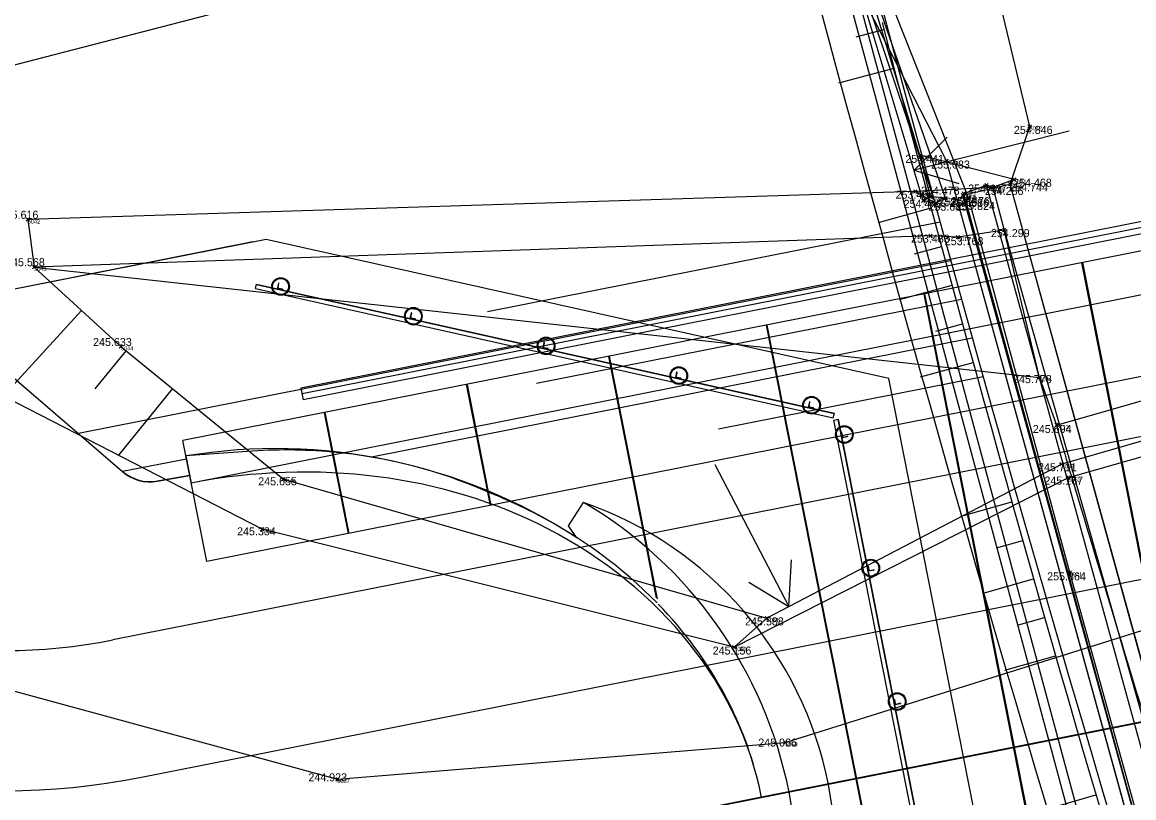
# Model space of a CAD drawing. Extents: x -809973 to -809318, y -1011363 to -1010505.
# Drawn here: x -809855.63 to -809841.74, y -1010988.6 to -1010978.91 of the extents above; entities that cross this region are included whole.
import ezdxf

# ---------------------------------------------------------------- set-up
doc = ezdxf.new("R2010")
doc.units = 0
for name, color, linetype in [('18b - zaměření - čísla bodů', 7, 'Continuous'), ('18c - zaměření - výšky', 7, 'Continuous'), ('21 - sítě', 7, 'Continuous'), ('21a - sítě - DKK - ČD Telematika a.s.', 7, 'Continuous'), ('21b - sítě - SŽDC - SSZT', 7, 'Continuous'), ('SO04 - Železniční spodek', 7, 'Continuous'), ('SO05 - Úprava kabelů', 7, 'Continuous'), ('SO_01', 7, 'Continuous'), ('stav_stav', 7, 'Continuous')]:
    doc.layers.add(name, color=color, linetype=linetype)

# ---------------------------------------------------------------- blocks, each defined once
blk = doc.blocks.new('POINT_DISPLAY')
for p, q in [((-0.021, -0.021), (0.021, 0.021)), ((-0.021, 0.021), (0.021, -0.021))]:
    blk.add_line(p, q)

msp = doc.modelspace()

# ---------------------------------------------------------------- linework, layer by layer
at = {"layer": '21 - sítě'}
msp.add_lwpolyline([(-809832.875, -1011017.263), (-809833.494, -1011015.746), (-809838.391, -1011005.426), (-809840.703, -1011001.729), (-809840.806, -1011000.123), (-809839.446, -1010997.434), (-809844.081, -1010980.644), (-809845.074, -1010978.711), (-809846.471, -1010977.412)], dxfattribs=at)
at = {"layer": '21a - sítě - DKK - ČD Telematika a.s.'}
msp.add_lwpolyline([(-809840.802, -1011000.183), (-809839.446, -1010997.434), (-809844.081, -1010980.644), (-809845.074, -1010978.711), (-809846.471, -1010977.412)], dxfattribs=at)
at = {"layer": '21b - sítě - SŽDC - SSZT'}
msp.add_lwpolyline([(-809840.802, -1011000.183), (-809839.446, -1010997.434), (-809844.081, -1010980.644), (-809845.074, -1010978.711), (-809846.471, -1010977.412)], dxfattribs=at)
at = {"layer": 'SO04 - Železniční spodek'}
for points in [[(-809845.21, -1010979.093), (-809844.863, -1010979.002)], [(-809845.426, -1010979.667), (-809844.736, -1010979.486)], [(-809844.932, -1010981.411), (-809844.272, -1010981.231)], [(-809844.479, -1010981.806), (-809844.142, -1010981.714)], [(-809844.669, -1010982.376), (-809844.011, -1010982.197)], [(-809844.214, -1010982.77), (-809843.88, -1010982.679)], [(-809844.407, -1010983.341), (-809843.747, -1010983.161)], [(-809843.896, -1010985.081), (-809843.263, -1010984.902)], [(-809843.455, -1010985.475), (-809843.128, -1010985.383)], [(-809843.624, -1010986.043), (-809842.992, -1010985.864)], [(-809843.179, -1010986.437), (-809842.854, -1010986.345)], [(-809843.352, -1010987.005), (-809842.717, -1010986.826)], [(-809842.826, -1010988.74), (-809842.213, -1010988.561)]]:
    msp.add_lwpolyline(points, dxfattribs=at)
for centre, radius, start, end in [((-809453.305, -1010872.818), 406.4, 193.63597, 201.43276), ((-809524.411, -1010895.31), 331.2, 194.62152, 202.36706)]:
    msp.add_arc(centre, radius, start, end, dxfattribs=at)
at = {"layer": 'SO05 - Úprava kabelů'}
for points in [[(-809832.452, -1011018.3), (-809834.599, -1011012.541), (-809836.558, -1011007.657), (-809839.63, -1011000.177), (-809840.754, -1010995.474), (-809845.885, -1010976.431), (-809847.466, -1010970.457), (-809849.998, -1010958.97), (-809853.746, -1010939.574), (-809862.448, -1010886.367), (-809861.681, -1010881.903), (-809870.184, -1010824.906)], [(-809832.343, -1011018.259), (-809834.49, -1011012.499), (-809836.45, -1011007.613), (-809839.519, -1011000.141), (-809840.641, -1010995.445), (-809845.773, -1010976.401), (-809847.353, -1010970.429), (-809849.884, -1010958.947), (-809853.631, -1010939.554), (-809862.33, -1010886.367), (-809861.563, -1010881.905), (-809870.069, -1010824.889)]]:
    msp.add_lwpolyline(points, dxfattribs=at)
at = {"layer": 'SO_01'}
for p, q in [((-809845.406, -1010976.768), (-809858.889, -1010980.268)), ((-809827.206, -1010978.912), (-809853.624, -1010984.137)), ((-809829.834, -1010979.065), (-809852.149, -1010983.48)), ((-809829.819, -1010979.139), (-809852.135, -1010983.553)), ((-809829.804, -1010979.213), (-809852.12, -1010983.627)), ((-809827.101, -1010979.442), (-809853.52, -1010984.667)), ((-809826.907, -1010980.423), (-809853.326, -1010985.648)), ((-809844.161, -1010981.408), (-809849.817, -1010982.527)), ((-809852.751, -1010981.656), (-809856.789, -1010982.455)), ((-809844.027, -1010981.891), (-809854.93, -1010984.048)), ((-809842.392, -1010981.916), (-809840.149, -1010993.254)), ((-809842.382, -1010981.914), (-809840.14, -1010993.252)), ((-809831.291, -1010982.037), (-809848.657, -1010985.472)), ((-809852.717, -1010982.239), (-809852.704, -1010982.181)), ((-809852.705, -1010982.186), (-809845.483, -1010983.8)), ((-809852.704, -1010982.181), (-809845.482, -1010983.795)), ((-809852.717, -1010982.239), (-809845.495, -1010983.853)), ((-809844.364, -1010982.306), (-809842.121, -1010993.644)), ((-809844.354, -1010982.304), (-809842.111, -1010993.642)), ((-809843.893, -1010982.374), (-809849.204, -1010983.425)), ((-809856.677, -1010982.547), (-809854.379, -1010984.522)), ((-809846.336, -1010982.696), (-809844.093, -1010994.034)), ((-809846.326, -1010982.694), (-809844.083, -1010994.032)), ((-809843.759, -1010982.857), (-809851.267, -1010984.342)), ((-809848.307, -1010983.086), (-809847.711, -1010986.1)), ((-809848.298, -1010983.084), (-809847.698, -1010986.114)), ((-809850.083, -1010983.437), (-809849.784, -1010984.948)), ((-809850.073, -1010983.435), (-809849.774, -1010984.946)), ((-809843.623, -1010983.34), (-809846.931, -1010983.995)), ((-809852.149, -1010983.48), (-809852.12, -1010983.627)), ((-809851.859, -1010983.788), (-809851.56, -1010985.299)), ((-809851.849, -1010983.786), (-809851.55, -1010985.297)), ((-809845.495, -1010983.853), (-809845.482, -1010983.795)), ((-809845.489, -1010983.883), (-809845.43, -1010983.871)), ((-809843.762, -1010992.614), (-809845.489, -1010983.883)), ((-809843.708, -1010992.603), (-809845.435, -1010983.872)), ((-809843.703, -1010992.602), (-809845.43, -1010983.871)), ((-809853.326, -1010985.648), (-809853.624, -1010984.137)), ((-809852.82, -1010984.272), (-809853.587, -1010984.329)), ((-809851.762, -1010984.279), (-809851.71, -1010984.541)), ((-809851.751, -1010984.28), (-809851.699, -1010984.541)), ((-809853.579, -1010984.369), (-809854.379, -1010984.522)), ((-809853.587, -1010984.329), (-809853.52, -1010984.667)), ((-809853.539, -1010984.571), (-809853.967, -1010984.646)), ((-809849.818, -1010984.777), (-809849.789, -1010984.922)), ((-809849.807, -1010984.782), (-809849.778, -1010984.926)), ((-809848.657, -1010985.472), (-809854.501, -1010986.627)), ((-809830.791, -1010985.512), (-809846.92, -1010988.702)), ((-809832.198, -1010985.784), (-809846.393, -1010988.591)), ((-809846.393, -1010988.591), (-809853.822, -1010990.061))]:
    msp.add_line(p, q, dxfattribs=at)
for points in [[(-809847.89, -1010966.747), (-809847.781, -1010967.211), (-809847.549, -1010968.191), (-809847.314, -1010969.171), (-809847.077, -1010970.15), (-809846.837, -1010971.129), (-809846.595, -1010972.108), (-809846.351, -1010973.086), (-809846.104, -1010974.063), (-809845.854, -1010975.04), (-809845.602, -1010976.016), (-809845.348, -1010976.992), (-809845.091, -1010977.967), (-809844.832, -1010978.937)], [(-809844.802, -1010983.363), (-809852.585, -1010981.623), (-809856.789, -1010982.455), (-809854.379, -1010984.522)], [(-809852.427, -1010982.171), (-809852.43, -1010982.17), (-809852.445, -1010982.239)], [(-809852.435, -1010982.225), (-809852.424, -1010982.176)], [(-809852.445, -1010982.239), (-809852.377, -1010982.254), (-809852.376, -1010982.252)], [(-809852.38, -1010982.246), (-809852.428, -1010982.235)], [(-809850.768, -1010982.542), (-809850.771, -1010982.541), (-809850.786, -1010982.609)], [(-809850.786, -1010982.609), (-809850.718, -1010982.625), (-809850.717, -1010982.622)], [(-809850.776, -1010982.595), (-809850.765, -1010982.547)], [(-809850.721, -1010982.617), (-809850.769, -1010982.606)], [(-809849.109, -1010982.912), (-809849.112, -1010982.912), (-809849.127, -1010982.98)], [(-809849.117, -1010982.966), (-809849.106, -1010982.918)], [(-809849.127, -1010982.98), (-809849.059, -1010982.996), (-809849.058, -1010982.993)], [(-809849.062, -1010982.988), (-809849.11, -1010982.977)], [(-809847.45, -1010983.283), (-809847.453, -1010983.283), (-809847.468, -1010983.351)], [(-809847.458, -1010983.337), (-809847.447, -1010983.289)], [(-809852.218, -1010995.743), (-809851.588, -1010997.824), (-809849.462, -1010997.404), (-809842.929, -1010992.833), (-809844.802, -1010983.363)], [(-809847.468, -1010983.351), (-809847.4, -1010983.366), (-809847.399, -1010983.364)], [(-809847.402, -1010983.358), (-809847.451, -1010983.348)], [(-809854.161, -1010988.344), (-809830.022, -1010983.57)], [(-809845.791, -1010983.654), (-809845.794, -1010983.654), (-809845.809, -1010983.722)], [(-809845.809, -1010983.722), (-809845.741, -1010983.737), (-809845.74, -1010983.735)], [(-809845.799, -1010983.708), (-809845.788, -1010983.659)], [(-809845.743, -1010983.729), (-809845.792, -1010983.718)], [(-809845.385, -1010984.102), (-809845.398, -1010984.033), (-809845.396, -1010984.033)], [(-809845.391, -1010984.036), (-809845.381, -1010984.085)], [(-809845.317, -1010984.086), (-809845.316, -1010984.088), (-809845.385, -1010984.102)], [(-809845.37, -1010984.092), (-809845.322, -1010984.082)], [(-809853.945, -1010984.642), (-809853.539, -1010984.571), (-809853.587, -1010984.329)], [(-809848.701, -1010985.35), (-809848.806, -1010985.202), (-809848.616, -1010984.908)], [(-809845.055, -1010985.769), (-809845.068, -1010985.701), (-809845.066, -1010985.7)], [(-809845.061, -1010985.704), (-809845.051, -1010985.752)], [(-809844.987, -1010985.753), (-809844.986, -1010985.756), (-809845.055, -1010985.769)], [(-809845.041, -1010985.759), (-809844.992, -1010985.75)], [(-809844.725, -1010987.437), (-809844.739, -1010987.368), (-809844.736, -1010987.368)], [(-809844.731, -1010987.371), (-809844.721, -1010987.42)], [(-809844.657, -1010987.421), (-809844.656, -1010987.424), (-809844.725, -1010987.437)], [(-809844.711, -1010987.427), (-809844.662, -1010987.418)]]:
    msp.add_lwpolyline(points, dxfattribs=at)
for centre, radius in [((-809852.403, -1010982.212), 0.11), ((-809852.403, -1010982.212), 0.1), ((-809850.744, -1010982.583), 0.11), ((-809850.744, -1010982.583), 0.1), ((-809849.085, -1010982.954), 0.11), ((-809849.085, -1010982.954), 0.1), ((-809847.426, -1010983.325), 0.11), ((-809847.426, -1010983.325), 0.1), ((-809845.767, -1010983.695), 0.11), ((-809845.767, -1010983.695), 0.1), ((-809845.357, -1010984.061), 0.11), ((-809845.357, -1010984.061), 0.1), ((-809845.027, -1010985.728), 0.11), ((-809845.027, -1010985.728), 0.1), ((-809844.697, -1010987.396), 0.11), ((-809844.697, -1010987.396), 0.1)]:
    msp.add_circle(centre, radius, dxfattribs=at)
for centre, radius, start, end in [((-809483.868, -1010882.207), 373.7, 195.00213, 199.87467), ((-809852.426, -1010982.227), 0.009, 167.4022, 257.4023), ((-809852.428, -1010982.175), 0.0045, 347.4022, 77.4023), ((-809852.381, -1010982.251), 0.0045, 347.4022, 77.4023), ((-809850.767, -1010982.597), 0.009, 167.4022, 257.4023), ((-809850.769, -1010982.546), 0.0045, 347.4022, 77.4023), ((-809850.722, -1010982.621), 0.0045, 347.4022, 77.4023), ((-809849.11, -1010982.917), 0.0045, 347.4022, 77.4023), ((-809849.108, -1010982.968), 0.009, 167.4022, 257.4023), ((-809849.063, -1010982.992), 0.0045, 347.4022, 77.4023), ((-809847.449, -1010983.339), 0.009, 167.4022, 257.4023), ((-809847.451, -1010983.288), 0.0045, 347.4022, 77.4023), ((-809847.403, -1010983.363), 0.0045, 347.4022, 77.4023), ((-809845.79, -1010983.71), 0.009, 167.4022, 257.4023), ((-809845.792, -1010983.658), 0.0045, 347.4022, 77.4023), ((-809845.744, -1010983.734), 0.0045, 347.4022, 77.4023), ((-809845.395, -1010984.037), 0.0045, 11.1885, 101.1886), ((-809845.372, -1010984.083), 0.009, 191.1885, 281.1886), ((-809845.321, -1010984.087), 0.0045, 11.1885, 101.1886), ((-809852.462, -1010991.148), 6.911, 57.0244, 99.3603), ((-809854.033, -1010984.118), 0.531, 229.3862, 279.4914), ((-809854.042, -1010984.152), 0.5, 227.6891, 281.1885), ((-809851.37, -1010989.582), 5.425, 322.8796, 59.4974), ((-809850.165, -1010989.344), 4.698, 311.6222, 70.7548), ((-809855.859, -1010979.76), 7, 237.1201, 281.1885), ((-809845.065, -1010985.705), 0.0045, 11.1885, 101.1886), ((-809845.042, -1010985.751), 0.009, 191.1885, 281.1886), ((-809844.991, -1010985.754), 0.0045, 11.1885, 101.1886), ((-809855.859, -1010979.76), 8.75, 237.1201, 281.1885), ((-809844.735, -1010987.372), 0.0045, 11.1885, 101.1886), ((-809844.712, -1010987.418), 0.009, 191.1885, 281.1886), ((-809844.661, -1010987.422), 0.0045, 11.1885, 101.1886), ((-809855.053, -1010979.444), 10.688, 234.89, 276.613)]:
    msp.add_arc(centre, radius, start, end, dxfattribs=at)
for centre, major_axis, ratio, start_param, end_param in [((-809852.609, -1010989.431), (5.722, 1.132), 0.882873, 1.251564, 1.434289), ((-809852.609, -1010989.431), (5.722, 1.132), 0.882873, 0.896781, 1.249758), ((-809852.612, -1010989.431), (5.947, 1.176), 0.8, 0.785398, 1.56521), ((-809852.98, -1010989.504), (6.315, 1.249), 0.8, 0.785398, 0.894584), ((-809853.381, -1010989.98), (6.99, 1.383), 0.8, 0.481469, 0.785398), ((-809853.013, -1010989.907), (6.622, 1.31), 0.8, 6.283185, 7.068583), ((-809853.381, -1010989.98), (6.99, 1.383), 0.800068, 0.000039, 0.478429)]:
    msp.add_ellipse(centre, major_axis=major_axis, ratio=ratio, start_param=start_param, end_param=end_param, dxfattribs=at)
at = {"layer": 'stav_stav'}
for p, q in [((-809843.041, -1010980.213), (-809846.285, -1010966.658)), ((-809843.802, -1010981.111), (-809844.97, -1010978.168)), ((-809844.371, -1010981.14), (-809845.223, -1010978.301)), ((-809844.216, -1010981.17), (-809845.209, -1010978.233)), ((-809844.216, -1010981.17), (-809845.209, -1010978.233)), ((-809844.412, -1010980.573), (-809845.115, -1010978.271)), ((-809844.412, -1010980.573), (-809845.115, -1010978.271)), ((-809844.092, -1010981.109), (-809845.085, -1010978.25)), ((-809844.081, -1010980.644), (-809845.074, -1010978.711)), ((-809842.546, -1010980.271), (-809844.486, -1010980.758)), ((-809843.283, -1010980.934), (-809843.041, -1010980.213)), ((-809844.282, -1010981.09), (-809844.412, -1010980.573)), ((-809843.235, -1010980.877), (-809844.412, -1010980.573)), ((-809839.446, -1010997.434), (-809844.081, -1010980.644)), ((-809843.503, -1010980.976), (-809844.471, -1010981.026)), ((-809843.876, -1010981.071), (-809843.283, -1010980.934)), ((-809843.865, -1010981.05), (-809843.582, -1010980.945)), ((-809843.582, -1010980.945), (-809843.503, -1010980.976)), ((-809839.075, -1010997.329), (-809843.582, -1010980.945)), ((-809843.235, -1010980.877), (-809843.503, -1010980.976)), ((-809843.503, -1010980.976), (-809843.358, -1010981.51)), ((-809843.283, -1010980.934), (-809843.235, -1010980.877)), ((-809843.283, -1010980.934), (-809843.235, -1010980.877)), ((-809838.806, -1010997.169), (-809843.283, -1010980.934)), ((-809838.806, -1010997.207), (-809843.283, -1010980.934)), ((-809838.806, -1010997.207), (-809843.283, -1010980.934)), ((-809844.471, -1010981.026), (-809855.563, -1010981.376)), ((-809844.471, -1010981.026), (-809855.563, -1010981.376)), ((-809844.216, -1010981.17), (-809844.471, -1010981.026)), ((-809844.371, -1010981.14), (-809844.282, -1010981.09)), ((-809844.092, -1010981.109), (-809844.282, -1010981.09)), ((-809844.092, -1010981.109), (-809844.216, -1010981.17)), ((-809843.876, -1010981.071), (-809843.865, -1010981.05)), ((-809839.345, -1010997.42), (-809843.876, -1010981.071)), ((-809839.358, -1010997.434), (-809843.865, -1010981.05)), ((-809842.539, -1010985.783), (-809843.802, -1010981.111)), ((-809844.216, -1010981.17), (-809844.371, -1010981.14)), ((-809855.563, -1010981.376), (-809855.483, -1010981.969)), ((-809855.563, -1010981.376), (-809855.483, -1010981.969)), ((-809843.358, -1010981.51), (-809843.938, -1010981.594)), ((-809842.919, -1010983.348), (-809843.358, -1010981.51)), ((-809843.358, -1010981.51), (-809839.041, -1010996.735)), ((-809844.28, -1010981.578), (-809855.483, -1010981.969)), ((-809843.938, -1010981.594), (-809844.28, -1010981.578)), ((-809855.483, -1010981.969), (-809842.919, -1010983.348)), ((-809855.483, -1010981.969), (-809854.399, -1010982.96)), ((-809854.89, -1010982.511), (-809855.863, -1010983.575)), ((-809842.705, -1010983.942), (-809837.764, -1010982.524)), ((-809854.334, -1010983.013), (-809854.723, -1010983.49)), ((-809854.399, -1010982.96), (-809852.369, -1010984.617)), ((-809837.836, -1010983.041), (-809842.641, -1010984.432)), ((-809842.555, -1010984.599), (-809837.625, -1010983.192)), ((-809842.919, -1010983.348), (-809842.705, -1010983.942)), ((-809852.633, -1010985.242), (-809855.833, -1010983.597)), ((-809853.753, -1010983.488), (-809854.431, -1010984.318)), ((-809846.977, -1010984.436), (-809846.052, -1010986.21)), ((-809842.641, -1010984.432), (-809846.327, -1010986.353)), ((-809852.369, -1010984.617), (-809846.327, -1010986.353)), ((-809846.733, -1010986.717), (-809842.555, -1010984.599)), ((-809846.095, -1010987.906), (-809837.047, -1010985.065)), ((-809846.733, -1010986.717), (-809852.633, -1010985.242)), ((-809839.322, -1010997.364), (-809842.539, -1010985.783)), ((-809846.327, -1010986.353), (-809846.733, -1010986.717)), ((-809846.327, -1010986.353), (-809846.733, -1010986.717)), ((-809856.273, -1010987.12), (-809851.693, -1010988.364)), ((-809851.693, -1010988.364), (-809846.095, -1010987.906))]:
    msp.add_line(p, q, dxfattribs=at)
for points in [[(-809844.074, -1010980.346), (-809844.486, -1010980.758), (-809843.927, -1010980.927)], [(-809846.549, -1010985.905), (-809846.052, -1010986.21), (-809846.017, -1010985.628)]]:
    msp.add_lwpolyline(points, dxfattribs=at)
msp.add_ellipse((-809841.093, -1010989.234), major_axis=(-1.62, 5.315), ratio=0.003059, start_param=6.189212, end_param=9.436189, dxfattribs=at)

# ---------------------------------------------------------------- block references
at = {"layer": '18b - zaměření - čísla bodů'}
for p in [(-809843.041, -1010980.213), (-809844.412, -1010980.573), (-809844.081, -1010980.644), (-809843.582, -1010980.945), (-809843.503, -1010980.976), (-809843.283, -1010980.934), (-809843.235, -1010980.877), (-809844.471, -1010981.026), (-809844.282, -1010981.09), (-809844.092, -1010981.109), (-809843.876, -1010981.071), (-809843.865, -1010981.05), (-809843.802, -1010981.111), (-809844.371, -1010981.14), (-809844.216, -1010981.17), (-809855.563, -1010981.376), (-809843.358, -1010981.51), (-809844.28, -1010981.578), (-809843.938, -1010981.594), (-809855.483, -1010981.969), (-809854.399, -1010982.96), (-809842.919, -1010983.348), (-809842.705, -1010983.942), (-809842.641, -1010984.432), (-809842.555, -1010984.599), (-809852.369, -1010984.617), (-809852.633, -1010985.242), (-809842.539, -1010985.783), (-809846.327, -1010986.353), (-809846.733, -1010986.717), (-809846.095, -1010987.906), (-809851.693, -1010988.364)]:
    msp.add_blockref('POINT_DISPLAY', p, dxfattribs=at)

# ---------------------------------------------------------------- texts
for s, p in [('5012', (-809843.041, -1010980.263)), ('5023', (-809844.412, -1010980.623)), ('5024', (-809844.081, -1010980.694)), ('7262', (-809843.582, -1010980.995)), ('5015', (-809843.503, -1010981.026)), ('5010', (-809843.283, -1010980.984)), ('5011', (-809843.235, -1010980.927)), ('5018', (-809844.471, -1010981.076)), ('5022', (-809844.282, -1010981.14)), ('5019', (-809844.092, -1010981.159)), ('5013', (-809843.876, -1010981.121)), ('5014', (-809843.865, -1010981.1)), ('5116', (-809843.802, -1010981.161)), ('5021', (-809844.371, -1010981.19)), ('5020', (-809844.216, -1010981.22)), ('5042', (-809855.563, -1010981.426)), ('1', (-809843.358, -1010981.56)), ('5017', (-809844.28, -1010981.628)), ('5016', (-809843.938, -1010981.644)), ('5043', (-809855.483, -1010982.019)), ('5044', (-809854.399, -1010983.01)), ('5064', (-809842.919, -1010983.398)), ('5113', (-809842.705, -1010983.992)), ('5063', (-809842.641, -1010984.482)), ('5049', (-809852.369, -1010984.667)), ('5062', (-809842.555, -1010984.649)), ('5048', (-809852.633, -1010985.292)), ('5041', (-809842.539, -1010985.833)), ('5061', (-809846.327, -1010986.403)), ('5060', (-809846.733, -1010986.767)), ('5058', (-809846.095, -1010987.956)), ('5057', (-809851.693, -1010988.414))]:
    msp.add_text(s, height=0.05, dxfattribs=at).set_placement(p)
at = {"layer": '18c - zaměření - výšky'}
for s, p in [('254.846', (-809843.238, -1010980.306)), ('254.441', (-809844.595, -1010980.668)), ('255.083', (-809844.272, -1010980.739)), ('254.478', (-809844.4, -1010981.065)), ('254.447', (-809843.81, -1010981.038)), ('254.286', (-809843.602, -1010981.069)), ('254.744', (-809843.296, -1010981.023)), ('254.468', (-809843.248, -1010980.966)), ('253.454', (-809844.717, -1010981.115)), ('253.785', (-809844.182, -1010981.204)), ('254.476', (-809844.022, -1010981.196)), ('254.443', (-809844.617, -1010981.229)), ('253.685', (-809844.306, -1010981.265)), ('254.686', (-809844.033, -1010981.217)), ('255.824', (-809843.959, -1010981.257)), ('245.616', (-809855.914, -1010981.366)), ('254.299', (-809843.525, -1010981.595)), ('253.483', (-809844.524, -1010981.664)), ('253.768', (-809844.102, -1010981.696)), ('245.568', (-809855.834, -1010981.959)), ('245.633', (-809854.747, -1010982.955)), ('245.778', (-809843.249, -1010983.419)), ('245.694', (-809843.001, -1010984.042)), ('245.711', (-809842.936, -1010984.519)), ('245.167', (-809842.857, -1010984.686)), ('245.655', (-809852.683, -1010984.695)), ('245.334', (-809852.947, -1010985.32)), ('255.864', (-809842.822, -1010985.882)), ('245.588', (-809846.598, -1010986.445)), ('245.156', (-809847.003, -1010986.809)), ('245.066', (-809846.433, -1010987.958)), ('244.923', (-809852.056, -1010988.392))]:
    msp.add_text(s, height=0.1, dxfattribs=at).set_placement(p)

doc.saveas('drawing.dxf')
